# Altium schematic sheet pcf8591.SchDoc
size A4
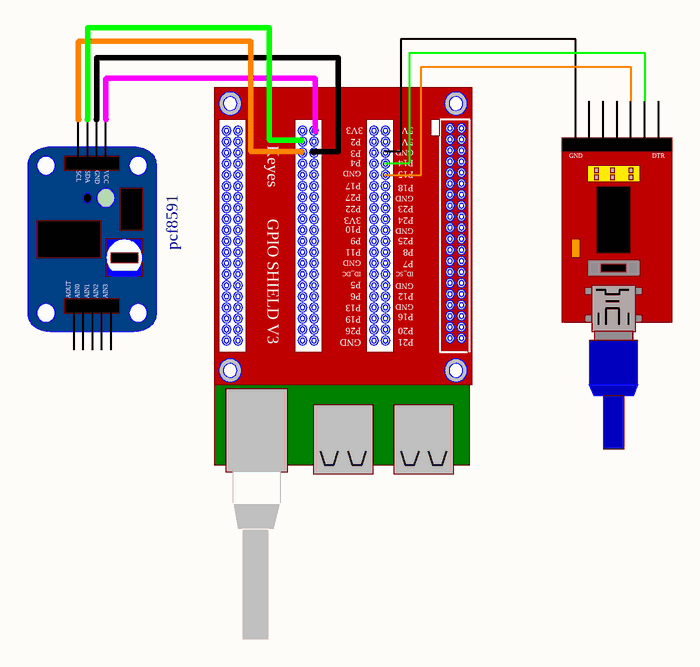
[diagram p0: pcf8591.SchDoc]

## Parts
0  pcf8591
2  raspberry-shield  (value not drawn)
4  FT232  (value not drawn)

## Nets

Not connected (* = marked no-connect by the designer): 0 33 34 35 36 37 38 39 40; 4 83 84 85 86 87 88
